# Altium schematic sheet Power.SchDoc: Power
size A4; Date: Not used; ApprovedBy: Not used; CheckedBy: Not used; Author: Not used; CompanyName: STMicroelectronics; DrawnBy: Not used; Engineer: Not used; Organization: Not used; Address1: Not used; Address2: Not used; Address3: Not used; Address4: Not used; DocumentNumber: Not used; Revision: Not used; SheetNumber: 5; SheetTotal: 6
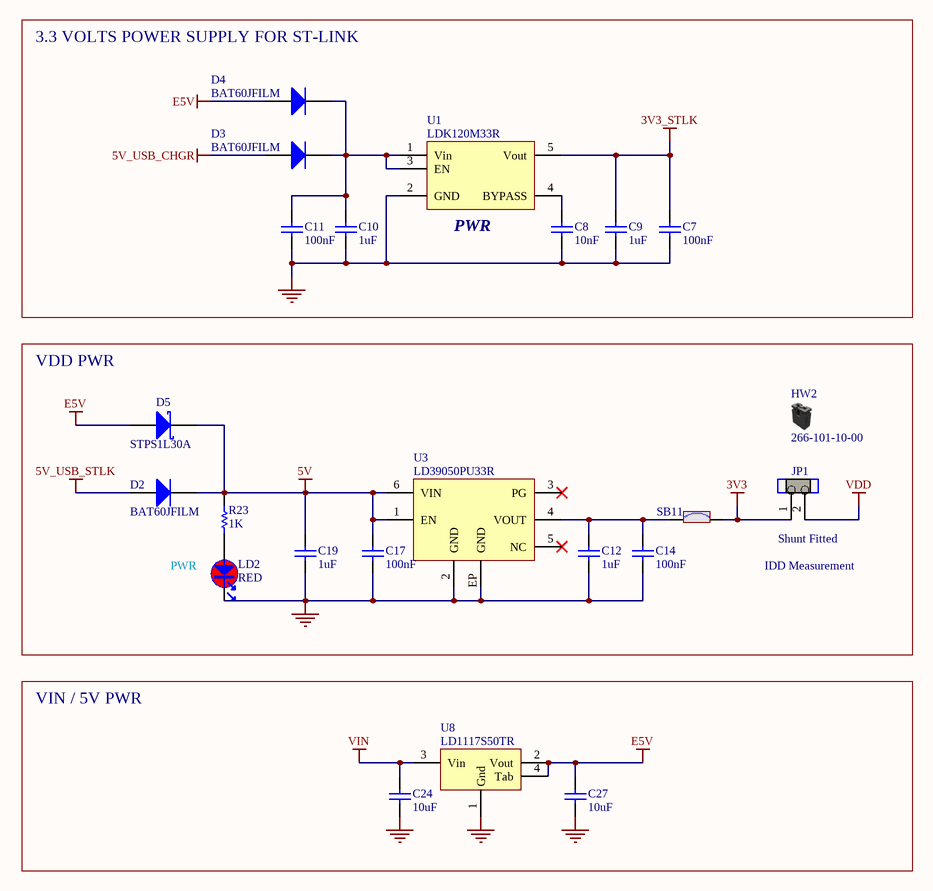
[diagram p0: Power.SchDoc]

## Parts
C7  value 100nF  [C0402]  (hidden comment: Capacitor)
C8  value 10nF  [C0402]  (hidden comment: Capacitor)
C9  value 1uF  [C0402]  (hidden comment: Capacitor)
C10  value 1uF  [C0402]  (hidden comment: Capacitor)
C11  value 100nF  [C0402]  (hidden comment: Capacitor)
C12  value 1uF  [C0402]  (hidden comment: Capacitor)
C14  value 100nF  [C0402]  (hidden comment: Capacitor)
C17  value 100nF  [C0402]  (hidden comment: Capacitor)
C19  value 1uF  [C0402]  (hidden comment: Capacitor)
C24  value 10uF  [C0805]  (hidden comment: Capacitor)
C27  value 10uF  [C0805]  (hidden comment: Capacitor)
D2  BAT60JFILM  [DIO_SOD323]
D3  BAT60JFILM  [DIO_SOD323]
D4  BAT60JFILM  [DIO_SOD323]
D5  value STPS1L30A  [DIO_SMA_1A_2K]  (hidden comment: STPS1L40M)
HW2  value 266-101-10-00  (hidden comment: Shunt Black 1.27mm 266-101-10-00)  (mechanical)
JP1  value Shunt Fitted  [CON_WP_707-2-02-2-20-00]  (hidden comment: Jumper_Header1.27 2x1 Fitted)
LD2  value RED  [LED_0603_RED_H0P4]  (hidden comment: LED_red)
R23  value 1K  [R0402]  (hidden comment: Resistor)
SB11  SB_ON  [SOLDER-BRIDGE_R0603-0R]  (value not drawn)
U1  LDK120M33R  [REG_SOT23-5L]
U3  LD39050PU33R  [ICC_DFN6-EPAD_3X3_P095]
U8  LD1117S50TR  [REG_SOT223-TAB]

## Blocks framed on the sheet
VDD PWR: C12 C14 C17 C19 D2 D5 HW2 JP1 LD2 R23 SB11 U3
VIN / 5V PWR: C24 C27 U8

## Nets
3V3: JP1.1 SB11.2
3V3_STLK: C7.2 C9.2 U1.5(Vout)
5V: C17.2 C19.2 D2.2(K) D5.2(K) R23.2 U3.1(EN) U3.6(VIN)
5V_USB_CHGR: D3.1(A)
5V_USB_STLK: D2.1(A)
E5V: C27.2 D4.1(A) D5.1(A) U8.2(Vout) U8.4(Tab)
GND: C7.1 C8.1 C9.1 C10.1 C11.1 C12.1 C14.1 C17.1 C19.1 C24.1 C27.1 LD2.2 U1.2(GND) U3.2(GND) U3.EP(GND) U8.1(Gnd)
VDD: JP1.2
VIN: C24.2 U8.3(Vin)
NetC8_2: C8.2 U1.4(BYPASS)
NetC10_2: C10.2 C11.2 D3.2(K) D4.2(K) U1.1(Vin) U1.3(EN)
NetC12_2: C12.2 C14.2 SB11.1 U3.4(VOUT)
NetLD2_1: LD2.1 R23.1

Not connected (* = marked no-connect by the designer): U3 3(PG)* 5(NC)*

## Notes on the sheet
- 3.3 VOLTS POWER SUPPLY FOR ST-LINK
- (near U1) PWR
- PWR
- IDD Measurement

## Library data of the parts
C7 C11 C14 C17 = MCD-00102: Capacitor, MLCC, 100nF, 16V, X7R, 10%, 0402, T=0,5mm; Manufacturer_Part_Number: CC0402KRX7R7BB104; Manufacturer: YAGEO; Alternate_Manufacturer_Part_Number: GCM155R71C104KA55D; Alternate_Manufacturer: MURATA; Provided_By: SUBCO; ECCN_US: EAR99; ECCN_EU: NEC
C8 = MCD-00011: Capacitor, MLCC, 10nF, 16V, X7R, 10%, 0402, T=0.5mm; Manufacturer_Part_Number: CC0402KRX7R7BB103; Manufacturer: YAGEO; Provided_By: SUBCO; ECCN_US: EAR99; ECCN_EU: NEC
C9 C10 C12 C19 = MCD-00095: Capacitor, MLCC, 1uF, 6V3, X5R, 10%, 0402, T=0,5mm; Manufacturer_Part_Number: GRM155R61E105KA12; Manufacturer: MURATA; Alternate_Manufacturer_Part_Number: GRM155R60J105KE19; Provided_By: SUBCO; ECCN_US: EAR99; ECCN_EU: NEC
C24 C27 = MCD-00014: Capacitor, MLCC, 10uF, 25V, X5R, 10%, 0805, T=0,85mm; Manufacturer_Part_Number: CC0805KRX5R8BB106; Manufacturer: YAGEO; Provided_By: SUBCO; ECCN_US: EAR99; ECCN_EU: NEC
D2-D4 = MCD-00034: Part_Type: Diode; Manufacturer: STMICROELECTRONICS; BMS_Part_Number: 9151097; ECCN_US: EAR99; ECCN_EU: NEC; Provided_By: SUBCO with ST control
D5 = MCD-01059: LOW DROP POWER SCHOTTKY RECTIFIER 1A 30V VF=0.3V; Part_Type: Diode; Manufacturer: STMICROELECTRONICS; BMS_Part_Number: 9151096; Provided_By: SUBCO with ST control; ECCN_US: EAR99; ECCN_EU: NEC
HW2 = MCD-01409: SHUNT 1.27mm BLACK; Part_Type: Mechanical; Manufacturer: W & P Products; Alternate_Manufacturer_Part_Number: M50-1900005; Alternate_Manufacturer: HARWIN; Provided_By: SUBCO
JP1 = MCD-01428: Header, 2x1, 1,27mm, Right Angled, Single Row, Height 3.05mm/1.27mm; Part_Type: Connector; Manufacturer_Part_Number: 707-2-02-2-20-00; Manufacturer: W & P Products; Provided_By: SUBCO
LD2 = MCD-00322: LED, Red, 0603; Manufacturer_Part_Number: 19-217/R6C-AL1M2VY/3T; Manufacturer: EVERLIGHT; Part_Type: Display; Provided_By: SUBCO; ECCN_US: EAR99; ECCN_EU: NEC
R23 = MCD-00061: Resistor,1K,0402,1%,1/16W; Manufacturer_Part_Number: RC0402FR-071KL; Manufacturer: YAGEO; Provided_By: SUBCO; ECCN_US: EAR99; ECCN_EU: NEC
SB11 = MCD-00071: Solder Bridge ON; Part_Type: Mechanical; Manufacturer_Part_Number: RC0603JR-070RL; Manufacturer: YAGEO; Provided_By: SUBCO
U1 = MCD-00663: 200 mA low quiescent current very low noise LDO; Part_Type: IC; Manufacturer: STMICROELECTRONICS; BMS_Part_Number: 9176330; ECCN_US: EAR99; ECCN_EU: NEC; Provided_By: SUBCO with ST control
U3 = MCD-00215: Low quiescent current and low noise voltage regulators; Manufacturer: STMICROELECTRONICS; Part_Type: IC; BMS_Part_Number: 9176126; Provided_By: SUBCO with ST control; ECCN_US: EAR99; ECCN_EU: NEC
U8 = MCD-00088: IC REG LDO 5V 0.8A SOT223; Manufacturer: STMICROELECTRONICS; BMS_Part_Number: 9176133; Provided_By: SUBCO with ST control; ECCN_US: EAR99; ECCN_EU: NEC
